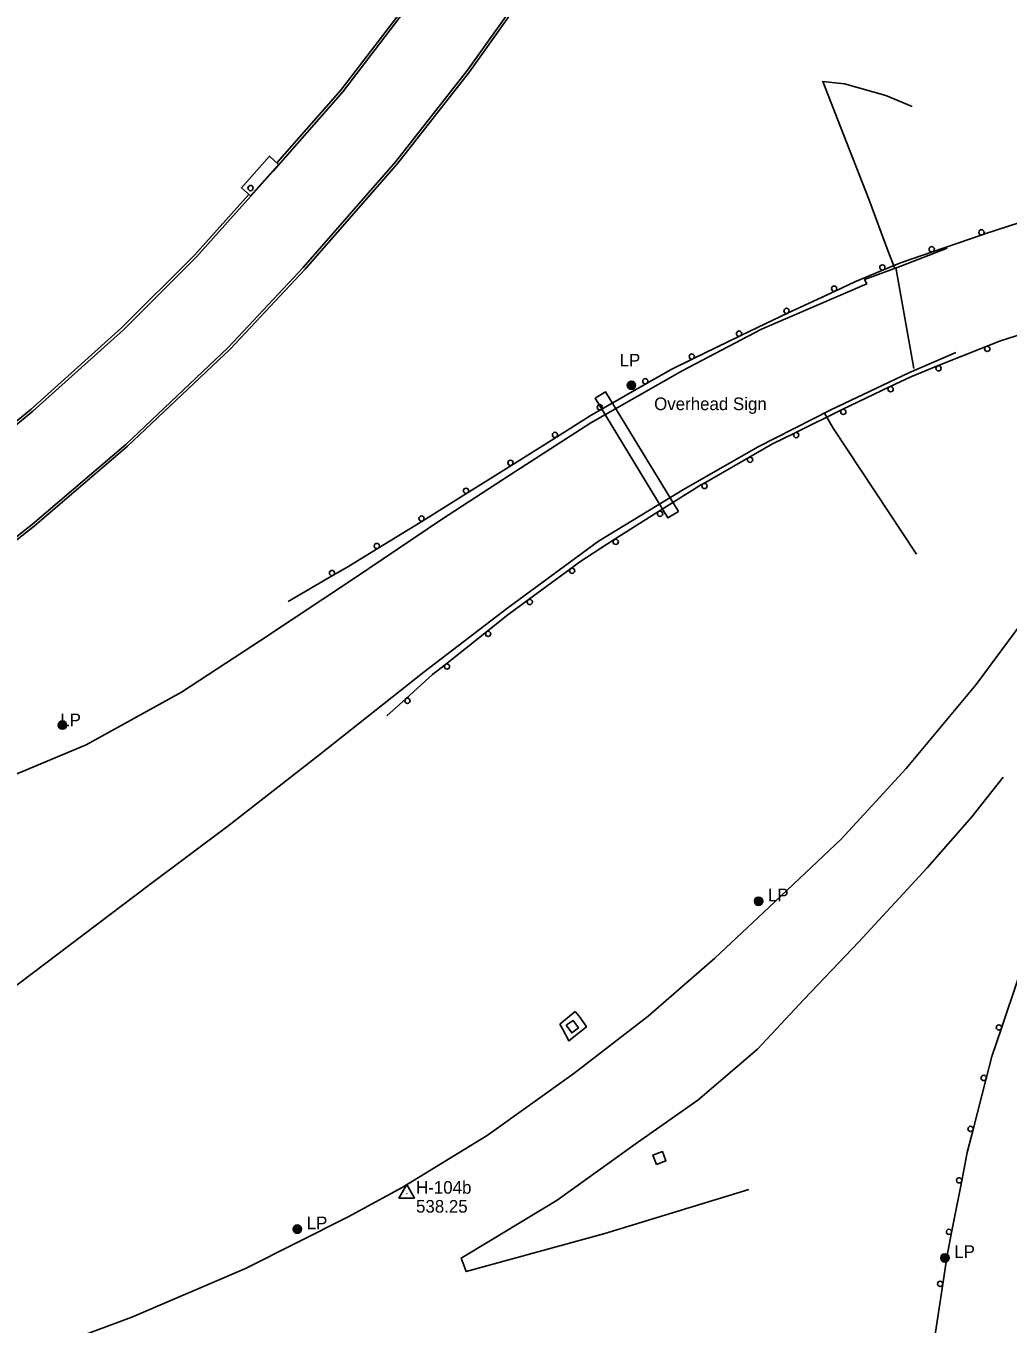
# Model space of a CAD drawing. Extents: x 2402803 to 2427059, y 6985292 to 6997652.
# Drawn here: x 2410013.2 to 2410386.7, y 6991556.2 to 6992049.7 of the extents above; entities that cross this region are included whole.
import ezdxf

# ---------------------------------------------------------------- set-up
doc = ezdxf.new("R2010")
doc.units = 0
for name, color, linetype in [('p_control ground ctrl', 7, 'Continuous'), ('p_drainage conc drain', 7, 'Continuous'), ('p_drainage riprap', 7, 'Continuous'), ('p_road - paved curb', 7, 'Continuous'), ('p_road bridge end', 7, 'Continuous'), ('p_road guard rails', 7, 'Continuous'), ('p_structure general', 7, 'Continuous'), ('p_utility manhole', 7, 'Continuous'), ('V7 LEVEL 31', 7, 'Continuous')]:
    doc.layers.add(name, color=color, linetype=linetype)

msp = doc.modelspace()

# ---------------------------------------------------------------- linework, layer by layer
at = {"layer": 'p_control ground ctrl'}
for p, q in [((2410158, 6991609.28), (2410155, 6991604.08)), ((2410161, 6991604.08), (2410158, 6991609.28)), ((2410155, 6991604.08), (2410161, 6991604.08)), ((2410158, 6991605.8), (2410158, 6991605.84))]:
    msp.add_line(p, q, dxfattribs=at)
at = {"layer": 'p_drainage conc drain'}
for points in [[(2410216.21, 6991670.29), (2410222.1, 6991675.07)], [(2410222.1, 6991675.07), (2410223.95, 6991672.76), (2410226.36, 6991669.23), (2410219.69, 6991663.87), (2410217.23, 6991668.42), (2410216.21, 6991670.29)]]:
    msp.add_lwpolyline(points, dxfattribs=at)
at = {"layer": 'p_drainage riprap'}
for points in [[(2410343.6, 6991957.54), (2410340.97, 6991964.39), (2410333.72, 6991983.9), (2410322.99, 6992011.39), (2410316.22, 6992028.69), (2410324.51, 6992027.77), (2410340.21, 6992023.32), (2410350.16, 6992019.17)], [(2410316.89, 6991902.58), (2410320.16, 6991896.89), (2410351.87, 6991848.91)]]:
    msp.add_lwpolyline(points, dxfattribs=at)
at = {"layer": 'p_road - paved curb'}
for points in [[(2409959.33, 6991858.12), (2409989.49, 6991881.68), (2410015.81, 6991903.28), (2410050.31, 6991934.27), (2410078.06, 6991961.92), (2410107.23, 6991994.6), (2410133.68, 6992024.69), (2410156.66, 6992054.68), (2410184.53, 6992094.35), (2410207.42, 6992130.63), (2410230.44, 6992170.39), (2410252.41, 6992212.43), (2410270.9, 6992253.75), (2410286.84, 6992293.96), (2410301.43, 6992336.59), (2410316.22, 6992382.9), (2410327.02, 6992421.55), (2410336.35, 6992455.45), (2410340.55, 6992472.49)], [(2410373.63, 6992472.15), (2410359.12, 6992413.99), (2410348.31, 6992376.6), (2410335.92, 6992336.84), (2410318.41, 6992286.2), (2410299.32, 6992237.8), (2410277.36, 6992190.38), (2410259.49, 6992155.68), (2410231.56, 6992108.32), (2410209.21, 6992072.47), (2410181.09, 6992032.9), (2410153.93, 6991998.27), (2410118.61, 6991957.93), (2410090.15, 6991927.54), (2410051.21, 6991890.67), (2410015.73, 6991860.29), (2409982.85, 6991834.66), (2409968.77, 6991824.37)], [(2410374.6, 6992471.91), (2410360.09, 6992413.73), (2410349.27, 6992376.31), (2410336.87, 6992336.53), (2410319.35, 6992285.85), (2410300.24, 6992237.41), (2410278.26, 6992189.94), (2410260.37, 6992155.2), (2410232.42, 6992107.8), (2410210.04, 6992071.92), (2410181.89, 6992032.3), (2410154.7, 6991997.63), (2410119.35, 6991957.26), (2410090.86, 6991926.83), (2410051.88, 6991889.93), (2410016.36, 6991859.52), (2409983.45, 6991833.86), (2409969.36, 6991823.56)], [(2410108.73, 6991997.82), (2410132.91, 6992025.32), (2410155.85, 6992055.27), (2410183.7, 6992094.9), (2410206.56, 6992131.15), (2410214.03, 6992144.05)], [(2409958.71, 6991858.91), (2409988.86, 6991882.46), (2410015.16, 6991904.04), (2410049.62, 6991935), (2410077.33, 6991962.61), (2410097.79, 6991985.52)], [(2409959.64, 6991745.55), (2409996.92, 6991760.12), (2410036.15, 6991776.39), (2410072.38, 6991796.41), (2410102.43, 6991816.12), (2410138.2, 6991839.78), (2410171.28, 6991862.09), (2410199.51, 6991880.55), (2410228.05, 6991898.83), (2410262.78, 6991918.62), (2410292.97, 6991934.53), (2410332.92, 6991951.71), (2410332.12, 6991953.33), (2410345.92, 6991958.39), (2410363.53, 6991965.25)], [(2409960.71, 6991529.81), (2410009.47, 6991542.48), (2410053.45, 6991558.8), (2410096.7, 6991577.41), (2410135.79, 6991596.98), (2410156.26, 6991608.22), (2410188.57, 6991627.97), (2410221.53, 6991651.53), (2410249.87, 6991673.26), (2410275.23, 6991695.32), (2410295.88, 6991714.67), (2410323.24, 6991740.62), (2410347.96, 6991767.42), (2410374.52, 6991799.38), (2410394.06, 6991825.68), (2410408.75, 6991847.33), (2410426.96, 6991877.43), (2410444.01, 6991908.91), (2410461.16, 6991944.99), (2410464.35, 6991952.1)], [(2410366.86, 6991925.56), (2410349.01, 6991917.9), (2410319.31, 6991903.81), (2410291.37, 6991889.56), (2410263.2, 6991873.55), (2410231, 6991853.85), (2410196.52, 6991828.47), (2410164.71, 6991804.22), (2410124.43, 6991772.41), (2410089.95, 6991745.52), (2410059.85, 6991722.95), (2410020.33, 6991693.12), (2409988.36, 6991668.97), (2409971.51, 6991657.64)], [(2410384.79, 6991764.16), (2410372.85, 6991749.04), (2410355.87, 6991729.69), (2410329.94, 6991701.54), (2410309.16, 6991679.77), (2410291.43, 6991660.78), (2410268.77, 6991641.37), (2410245.77, 6991625.24), (2410215.2, 6991603.39), (2410189.83, 6991587.99), (2410178.76, 6991581.23), (2410180.67, 6991576.2), (2410233.36, 6991590.72), (2410288.05, 6991607.35)]]:
    msp.add_lwpolyline(points, dxfattribs=at)
at = {"layer": 'p_road bridge end'}
for points in [[(2410098.65, 6991985.14), (2410109.28, 6991997.07), (2410105.78, 6992000.19), (2410095.15, 6991988.26)], [(2410218.67, 6991669.83), (2410221.25, 6991671.69), (2410223.33, 6991668.81), (2410220.75, 6991666.95)], [(2410252.97, 6991616.92), (2410256.57, 6991618.27), (2410255.23, 6991621.83), (2410251.63, 6991620.48)]]:
    msp.add_lwpolyline(points, close=True, dxfattribs=at)
msp.add_lwpolyline([(2410350.91, 6991919.5), (2410344, 6991957.92)], dxfattribs=at)
at = {"layer": 'p_road guard rails'}
for p, q in [((2410357.99, 6991963.89), (2410376.87, 6991970.33)), ((2410302.87, 6991940.5), (2410320.97, 6991948.98)), ((2410266.85, 6991923.15), (2410284.84, 6991931.88)), ((2410378.41, 6991927.91), (2410359.86, 6991920.49)), ((2410231.93, 6991903.93), (2410249.24, 6991913.8)), ((2410341.57, 6991912.54), (2410323.6, 6991903.93)), ((2410198.01, 6991882.8), (2410214.93, 6991893.45)), ((2410288.08, 6991885.67), (2410270.75, 6991875.72)), ((2410164.19, 6991861.6), (2410181.1, 6991872.2)), ((2410220.3, 6991843.42), (2410204.21, 6991831.55)), ((2410112.94, 6991830.88), (2410130.1, 6991840.9)), ((2410188.35, 6991819.4), (2410172.7, 6991806.99)), ((2410157.62, 6991793.97), (2410150.4, 6991787.49)), ((2410384.15, 6991668.69), (2410390.5, 6991687.66)), ((2410373.4, 6991630.19), (2410378.39, 6991649.55)), ((2410365.2, 6991591.1), (2410369.04, 6991610.7))]:
    msp.add_line(p, q, dxfattribs=at)
for points in [[(2410376.87, 6991970.33), (2410377.83, 6991970.66), (2410395.87, 6991976.57)], [(2410339.26, 6991957), (2410345.78, 6991959.73), (2410357.99, 6991963.89)], [(2410320.97, 6991948.98), (2410328.43, 6991952.47), (2410339.26, 6991957)], [(2410284.84, 6991931.88), (2410294.3, 6991936.48), (2410302.87, 6991940.5)], [(2410397.34, 6991934.29), (2410383.78, 6991930.06), (2410378.41, 6991927.91)], [(2410249.24, 6991913.8), (2410258.59, 6991919.13), (2410266.85, 6991923.15)], [(2410359.86, 6991920.49), (2410349.65, 6991916.41), (2410341.57, 6991912.54)], [(2410214.93, 6991893.45), (2410228.17, 6991901.78), (2410231.93, 6991903.93)], [(2410323.6, 6991903.93), (2410323.59, 6991903.93), (2410305.68, 6991895.09)], [(2410305.68, 6991895.09), (2410297.09, 6991890.85), (2410288.08, 6991885.67)], [(2410181.1, 6991872.2), (2410194.97, 6991880.89), (2410198.01, 6991882.8)], [(2410270.75, 6991875.72), (2410270.17, 6991875.39), (2410253.82, 6991865.16)], [(2410253.82, 6991865.16), (2410247.98, 6991861.51), (2410236.96, 6991854.45)], [(2410147.18, 6991851.17), (2410160.88, 6991859.53), (2410164.19, 6991861.6)], [(2410236.96, 6991854.45), (2410223.88, 6991846.06), (2410220.3, 6991843.42)], [(2410130.1, 6991840.9), (2410135.63, 6991844.13), (2410147.18, 6991851.17)], [(2410204.21, 6991831.55), (2410196.44, 6991825.82), (2410188.35, 6991819.4)], [(2410172.7, 6991806.99), (2410167.86, 6991803.15), (2410157.62, 6991793.97)], [(2410378.39, 6991649.55), (2410380.56, 6991657.95), (2410384.15, 6991668.69)], [(2410369.04, 6991610.7), (2410371.16, 6991621.5), (2410373.4, 6991630.19)], [(2410361.84, 6991571.4), (2410363.36, 6991581.71), (2410365.2, 6991591.1)], [(2410358.97, 6991551.61), (2410359.15, 6991553.12), (2410361.84, 6991571.4)]]:
    msp.add_lwpolyline(points, dxfattribs=at)
for centre in [(2410376.55, 6991971.28), (2410357.66, 6991964.84), (2410338.88, 6991957.93), (2410320.55, 6991949.88), (2410302.45, 6991941.4), (2410284.4, 6991932.78), (2410378.78, 6991926.98), (2410266.42, 6991924.04), (2410360.24, 6991919.57), (2410248.74, 6991914.66), (2410342.01, 6991911.64), (2410231.44, 6991904.79), (2410324.03, 6991903.03), (2410214.39, 6991894.29), (2410306.13, 6991894.19), (2410197.47, 6991883.65), (2410288.57, 6991884.81), (2410180.57, 6991873.04), (2410271.25, 6991874.86), (2410163.66, 6991862.45), (2410254.35, 6991864.31), (2410146.66, 6991852.03), (2410237.5, 6991853.61), (2410220.9, 6991842.62), (2410129.59, 6991841.76), (2410204.81, 6991830.75), (2410188.97, 6991818.62), (2410173.32, 6991806.21), (2410158.29, 6991793.22), (2410383.21, 6991669.01), (2410377.43, 6991649.8), (2410372.43, 6991630.44), (2410368.06, 6991610.89), (2410364.22, 6991591.29), (2410360.85, 6991571.55)]:
    msp.add_circle(centre, 1, dxfattribs=at)
at = {"layer": 'p_structure general'}
msp.add_lwpolyline([(2410261.34, 6991865.17), (2410233.65, 6991910.64), (2410229.67, 6991908.21), (2410257.36, 6991862.74)], close=True, dxfattribs=at)
msp.add_circle((2410098.64, 6991988.11), 1, dxfattribs=at)
at = {"layer": 'p_utility manhole'}
for centre, radius in [((2410243.46, 6991913.12), 1.6), ((2410243.46, 6991913.12), 1.3), ((2410243.46, 6991913.12), 1), ((2410243.46, 6991913.12), 0.539), ((2410243.46, 6991913.12), 0.192), ((2410027.1, 6991783.96), 1.6), ((2410027.1, 6991783.96), 1.3), ((2410027.1, 6991783.96), 1), ((2410027.1, 6991783.96), 0.539), ((2410027.1, 6991783.96), 0.192), ((2410291.82, 6991716.98), 1.6), ((2410291.82, 6991716.98), 1.3), ((2410291.82, 6991716.98), 1), ((2410291.82, 6991716.98), 0.539), ((2410291.82, 6991716.98), 0.192), ((2410116.42, 6991592.31), 1.6), ((2410116.42, 6991592.31), 1.3), ((2410116.42, 6991592.31), 1), ((2410116.42, 6991592.31), 0.539), ((2410116.42, 6991592.31), 0.192), ((2410362.67, 6991581.38), 1.6), ((2410362.67, 6991581.38), 1.3), ((2410362.67, 6991581.38), 1), ((2410362.67, 6991581.38), 0.539), ((2410362.67, 6991581.38), 0.192)]:
    msp.add_circle(centre, radius, dxfattribs=at)

# ---------------------------------------------------------------- texts
at = {"layer": 'p_control ground ctrl'}
msp.add_text('  H-104b', height=4.8, dxfattribs=at).set_placement((2410158, 6991605.8))
at = {"layer": 'p_structure general'}
msp.add_text('Overhead Sign', height=4.8, dxfattribs=at).set_placement((2410252.1, 6991903.69))
at = {"layer": 'p_utility manhole'}
for p in [(2410235.41, 6991920.29), (2410022.7, 6991783.54), (2410291.82, 6991716.98), (2410116.42, 6991592.31), (2410362.67, 6991581.38)]:
    msp.add_text('  LP', height=4.8, dxfattribs=at).set_placement(p)
at = {"layer": 'V7 LEVEL 31'}
msp.add_text('  538.25', height=4.8, dxfattribs=at).set_placement((2410158, 6991598.6))

doc.saveas('drawing.dxf')
